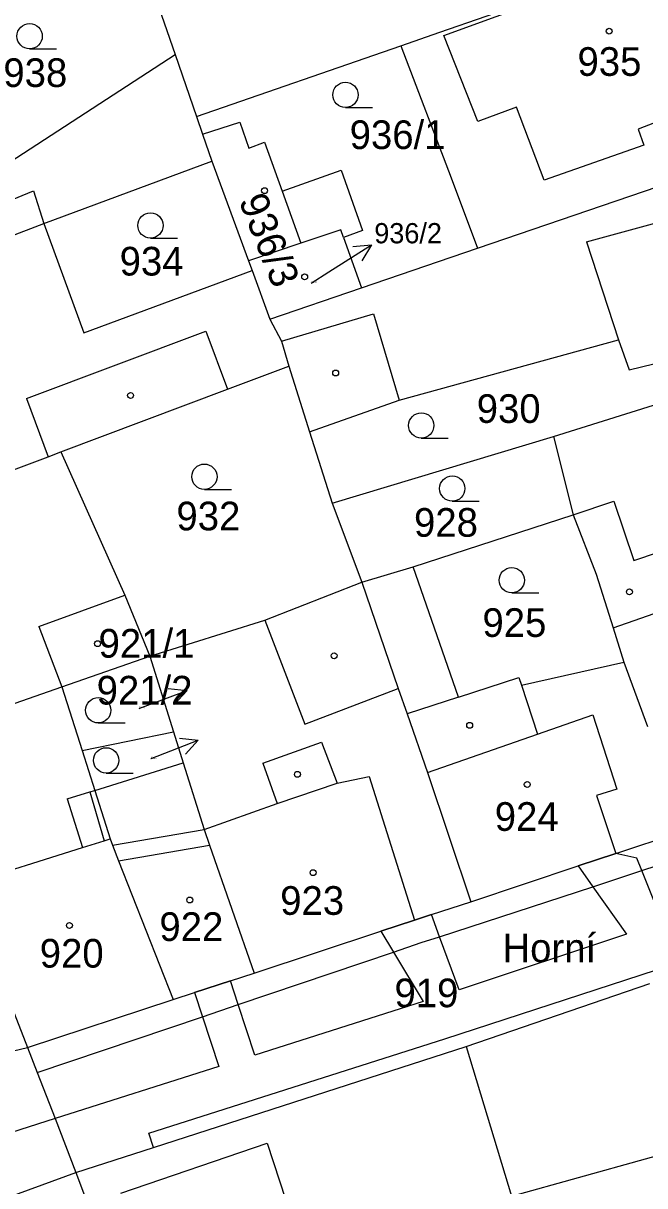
# Model space of a CAD drawing. Extents: x -785744 to -782822, y -1067550 to -1063910.
# Drawn here: x -783686.8 to -783649.9, y -1066020.9 to -1065951.9 of the extents above; entities that cross this region are included whole.
import ezdxf

# ---------------------------------------------------------------- set-up
doc = ezdxf.new("R2010")
doc.units = 0
for name, color, linetype in [('Hranice parcel', 7, 'Continuous'), ('Parcelní čísla', 7, 'Continuous'), ('Pop_ČP_popisy', 7, 'Continuous'), ('Vnitřní kresba', 7, 'Continuous'), ('Věcná břemena k části', 7, 'Continuous'), ('Značky budov', 7, 'Continuous'), ('Značky kultur', 7, 'Continuous')]:
    doc.layers.add(name, color=color, linetype=linetype)

msp = doc.modelspace()

# ---------------------------------------------------------------- linework, layer by layer
at = {"layer": 'Hranice parcel'}
for p, q in [((-783676.54, -1065957.47), (-783676.18, -1065958.51)), ((-783676.18, -1065958.51), (-783673.97, -1065957.81)), ((-783673.97, -1065957.81), (-783673.43, -1065959.34)), ((-783676.18, -1065958.51), (-783675.63, -1065960.11)), ((-783673.43, -1065959.34), (-783672.5, -1065959)), ((-783672.5, -1065959), (-783671.45, -1065961.89)), ((-783675.63, -1065960.11), (-783673.45, -1065966.02)), ((-783671.45, -1065961.89), (-783667.95, -1065960.66)), ((-783667.95, -1065960.66), (-783666.68, -1065964.23)), ((-783667.98, -1065964.19), (-783670.34, -1065964.98)), ((-783667.82, -1065964.64), (-783667.98, -1065964.19)), ((-783666.68, -1065964.23), (-783667.82, -1065964.64)), ((-783667.82, -1065964.64), (-783666.74, -1065967.63)), ((-783670.34, -1065964.98), (-783673.45, -1065966.02)), ((-783666.74, -1065967.63), (-783659.86, -1065965.28)), ((-783673.45, -1065966.02), (-783673.23, -1065966.61)), ((-783672.18, -1065969.49), (-783666.74, -1065967.63)), ((-783660.99, -1065991.9), (-783663.69, -1065984.17)), ((-783657.25, -1065991.2), (-783651.17, -1065989.82)), ((-783660.99, -1065991.9), (-783657.41, -1065990.73)), ((-783657.41, -1065990.73), (-783657.25, -1065991.2)), ((-783664.57, -1065991.38), (-783664.04, -1065992.9)), ((-783664.04, -1065992.9), (-783662.84, -1065996.36))]:
    msp.add_line(p, q, dxfattribs=at)
for points in [[(-783680.07, -1065947.23), (-783677.8, -1065953.8)], [(-783662.09, -1065952.47), (-783656.6, -1065950.57)], [(-783664.42, -1065953.28), (-783662.09, -1065952.47)], [(-783676.54, -1065957.47), (-783664.42, -1065953.28)], [(-783664.42, -1065953.28), (-783661.42, -1065961.11)], [(-783690.51, -1065962.03), (-783677.8, -1065953.8)], [(-783677.8, -1065953.8), (-783676.54, -1065957.47)], [(-783659.86, -1065965.28), (-783643.4, -1065959.66)], [(-783685.59, -1065963.82), (-783675.63, -1065960.11)], [(-783661.42, -1065961.11), (-783659.86, -1065965.28)], [(-783690.3, -1065965.62), (-783685.59, -1065963.82)], [(-783685.59, -1065963.82), (-783683.22, -1065970.29)], [(-783683.22, -1065970.29), (-783673.23, -1065966.61)], [(-783673.23, -1065966.61), (-783672.18, -1065969.49)], [(-783672.18, -1065969.49), (-783671.5, -1065970.8)], [(-783671.5, -1065970.8), (-783671.05, -1065972.27)], [(-783664.52, -1065974.29), (-783651.5, -1065970.71)], [(-783651.5, -1065970.71), (-783650.86, -1065972.5)], [(-783650.86, -1065972.5), (-783646.4, -1065971.4)], [(-783674.7, -1065973.64), (-783671.05, -1065972.27)], [(-783671.05, -1065972.27), (-783669.84, -1065976.17)], [(-783684.59, -1065977.36), (-783674.7, -1065973.64)], [(-783669.84, -1065976.17), (-783664.52, -1065974.29)], [(-783655.35, -1065976.45), (-783646.45, -1065973.65)], [(-783669.84, -1065976.17), (-783668.49, -1065980.39)], [(-783668.49, -1065980.39), (-783655.35, -1065976.45)], [(-783655.35, -1065976.45), (-783654.18, -1065981.09)], [(-783689.79, -1065979.32), (-783685.34, -1065977.65)], [(-783685.34, -1065977.65), (-783684.59, -1065977.36)], [(-783684.59, -1065977.36), (-783680.8, -1065985.85)], [(-783668.49, -1065980.39), (-783666.72, -1065985.08)], [(-783663.69, -1065984.17), (-783654.18, -1065981.09)], [(-783654.18, -1065981.09), (-783652.83, -1065984.61)], [(-783666.72, -1065985.08), (-783663.69, -1065984.17)], [(-783652.83, -1065984.61), (-783651.82, -1065987.8)], [(-783672.48, -1065987.34), (-783666.72, -1065985.08)], [(-783666.72, -1065985.08), (-783664.57, -1065991.38)], [(-783680.8, -1065985.85), (-783679.3, -1065989.47)], [(-783651.82, -1065987.8), (-783648.13, -1065986.51)], [(-783679.3, -1065989.47), (-783672.48, -1065987.34)], [(-783651.82, -1065987.8), (-783651.17, -1065989.82)], [(-783684.53, -1065991.29), (-783679.3, -1065989.47)], [(-783679.3, -1065989.47), (-783677.9, -1065993.96)], [(-783651.17, -1065989.82), (-783649.78, -1065993.65)], [(-783691.34, -1065993.67), (-783684.53, -1065991.29)], [(-783684.53, -1065991.29), (-783683.33, -1065995.06)], [(-783683.33, -1065995.06), (-783677.9, -1065993.96)], [(-783677.9, -1065993.96), (-783677.33, -1065995.79)], [(-783683.33, -1065995.06), (-783682.58, -1065997.43)], [(-783682.58, -1065997.43), (-783677.33, -1065995.79)], [(-783677.33, -1065995.79), (-783676.09, -1065999.75)], [(-783662.84, -1065996.36), (-783660.26, -1066004.04)], [(-783682.58, -1065997.43), (-783681.67, -1066000.31)], [(-783676.09, -1065999.75), (-783675.76, -1066000.67)], [(-783681.67, -1066000.31), (-783681.52, -1066000.68)], [(-783651.66, -1066001.17), (-783647.96, -1065999.94)], [(-783681.52, -1066000.68), (-783681.16, -1066001.6)], [(-783675.76, -1066000.67), (-783673.12, -1066008.26)], [(-783660.26, -1066004.04), (-783653.88, -1066001.91), (-783651.66, -1066001.17)], [(-783681.16, -1066001.6), (-783677.93, -1066009.84)], [(-783690.35, -1066003.03), (-783689.72, -1066004.62), (-783688.9, -1066006.72), (-783686.56, -1066012.68)], [(-783663.61, -1066005.13), (-783662.6, -1066004.8), (-783660.26, -1066004.04)], [(-783673.12, -1066008.26), (-783665.59, -1066005.78), (-783663.61, -1066005.13)], [(-783677.93, -1066009.84), (-783676.66, -1066009.42), (-783674.53, -1066008.72), (-783673.12, -1066008.26)], [(-783660.54, -1066012.61), (-783649.64, -1066008.89)], [(-783686.56, -1066012.68), (-783677.93, -1066009.84)], [(-783689.58, -1066013.38), (-783686.56, -1066012.68)], [(-783686.56, -1066012.68), (-783685.99, -1066014.16)], [(-783683.69, -1066020.08), (-783679.09, -1066018.6), (-783660.54, -1066012.61)], [(-783660.54, -1066012.61), (-783657.85, -1066021.5)], [(-783685.99, -1066014.16), (-783684.93, -1066016.89), (-783683.69, -1066020.08)], [(-783681.03, -1066021.32), (-783672.35, -1066018.35)], [(-783672.35, -1066018.35), (-783669.78, -1066026.19)], [(-783657.85, -1066021.5), (-783645.91, -1066018.18)], [(-783683.69, -1066020.08), (-783680.11, -1066029.6)]]:
    msp.add_lwpolyline(points, dxfattribs=at)
at = {"layer": 'Pop_ČP_popisy'}
for p, q in [((-783668.68, -1065966.68), (-783666.144, -1065965.077)), ((-783679.91, -1065992.56), (-783677.098, -1065991.514)), ((-783679.23, -1065995.53), (-783676.432, -1065994.448))]:
    msp.add_line(p, q, dxfattribs=at)
for points in [[(-783667.257, -1065965.188), (-783666.144, -1065965.077), (-783666.722, -1065966.034)], [(-783669.74, -1065967.35), (-783668.68, -1065966.68)], [(-783678.21, -1065991.394), (-783677.098, -1065991.514), (-783677.861, -1065992.331)], [(-783679.95, -1065992.57), (-783679.91, -1065992.56)], [(-783677.545, -1065994.343), (-783676.432, -1065994.448), (-783677.184, -1065995.275)], [(-783679.25, -1065995.54), (-783679.23, -1065995.53)]]:
    msp.add_lwpolyline(points, dxfattribs=at)
at = {"layer": 'Vnitřní kresba'}
for p, q in [((-783661.86, -1065952.67), (-783647.99, -1065947.6)), ((-783659.84, -1065957.76), (-783661.86, -1065952.67)), ((-783644.83, -1065956.05), (-783650.33, -1065958.23)), ((-783657.54, -1065956.92), (-783659.84, -1065957.76)), ((-783655.9, -1065961.25), (-783657.54, -1065956.92)), ((-783650.33, -1065958.23), (-783650, -1065959.17)), ((-783650, -1065959.17), (-783655.9, -1065961.25)), ((-783671.45, -1065961.89), (-783670.34, -1065964.98)), ((-783657.25, -1065991.2), (-783656.3, -1065994.1)), ((-783660.99, -1065991.9), (-783664.04, -1065992.9)), ((-783656.3, -1065994.1), (-783653.01, -1065992.96)), ((-783653.01, -1065992.96), (-783651.6, -1065997.35)), ((-783662.84, -1065996.36), (-783656.3, -1065994.1)), ((-783651.6, -1065997.35), (-783652.8, -1065997.73)), ((-783652.8, -1065997.73), (-783651.66, -1066001.17))]:
    msp.add_line(p, q, dxfattribs=at)
for points in [[(-783690.97, -1065963.83), (-783686.22, -1065961.88)], [(-783686.22, -1065961.88), (-783685.59, -1065963.82)], [(-783653.4, -1065964.9), (-783648.6, -1065963.6)], [(-783653.4, -1065964.9), (-783651.5, -1065970.71)], [(-783671.5, -1065970.8), (-783666.03, -1065969.18)], [(-783666.03, -1065969.18), (-783664.52, -1065974.29)], [(-783686.63, -1065974.2), (-783675.99, -1065970.2)], [(-783675.99, -1065970.2), (-783674.7, -1065973.64)], [(-783686.63, -1065974.2), (-783685.34, -1065977.65)], [(-783654.18, -1065981.09), (-783651.77, -1065980.28)], [(-783651.77, -1065980.28), (-783650.59, -1065983.79)], [(-783650.59, -1065983.79), (-783647.72, -1065982.83)], [(-783685.9, -1065987.72), (-783680.8, -1065985.85)], [(-783672.48, -1065987.34), (-783670.1, -1065993.51)], [(-783685.9, -1065987.72), (-783684.53, -1065991.29)], [(-783670.1, -1065993.51), (-783664.57, -1065991.38)], [(-783672.6, -1065995.81), (-783669.12, -1065994.58)], [(-783669.12, -1065994.58), (-783668.2, -1065997)], [(-783663.2, -1066006.46), (-783662.12, -1066006.11), (-783653.01, -1066003.14), (-783650.11, -1066002.19), (-783629.52, -1065995.48)], [(-783672.6, -1065995.81), (-783671.75, -1065998.21)], [(-783671.75, -1065998.21), (-783668.2, -1065997)], [(-783668.2, -1065997), (-783666.3, -1065996.6)], [(-783666.3, -1065996.6), (-783663.61, -1066005.13)], [(-783684.21, -1065997.94), (-783682.87, -1065997.52)], [(-783682.87, -1065997.52), (-783682.58, -1065997.43)], [(-783682.87, -1065997.52), (-783682.01, -1066000.42)], [(-783684.21, -1065997.94), (-783683.31, -1066000.82)], [(-783676.09, -1065999.75), (-783671.75, -1065998.21)], [(-783681.52, -1066000.68), (-783676.09, -1065999.75)], [(-783683.31, -1066000.82), (-783682.01, -1066000.42)], [(-783682.01, -1066000.42), (-783681.67, -1066000.31)], [(-783690.35, -1066003.03), (-783683.31, -1066000.82)], [(-783681.16, -1066001.6), (-783675.76, -1066000.67)], [(-783685.99, -1066014.16), (-783676.19, -1066010.85), (-783674.06, -1066010.13), (-783664.85, -1066007.02), (-783663.2, -1066006.46)]]:
    msp.add_lwpolyline(points, dxfattribs=at)
at = {"layer": 'Věcná břemena k části'}
for points in [[(-783651.66, -1066001.17), (-783653.88, -1066001.91)], [(-783650.41, -1066001.44), (-783651.66, -1066001.17)], [(-783650.11, -1066002.19), (-783650.41, -1066001.44)], [(-783661.81, -1066012.17), (-783630.43, -1066001.95)], [(-783653.88, -1066001.91), (-783653.01, -1066003.14)], [(-783648.88, -1066005.24), (-783650.11, -1066002.19)], [(-783653.01, -1066003.14), (-783651.02, -1066005.95)], [(-783663.61, -1066005.13), (-783665.59, -1066005.78)], [(-783662.6, -1066004.8), (-783663.61, -1066005.13)], [(-783662.12, -1066006.11), (-783662.6, -1066004.8)], [(-783665.59, -1066005.78), (-783664.85, -1066007.02)], [(-783651.02, -1066005.95), (-783660.95, -1066009.25)], [(-783660.95, -1066009.25), (-783662.12, -1066006.11)], [(-783664.85, -1066007.02), (-783663.09, -1066009.95)], [(-783674.53, -1066008.72), (-783676.66, -1066009.42)], [(-783674.06, -1066010.13), (-783674.53, -1066008.72)], [(-783676.66, -1066009.42), (-783676.19, -1066010.85)], [(-783673.07, -1066013.13), (-783674.06, -1066010.13)], [(-783663.09, -1066009.95), (-783673.07, -1066013.13)], [(-783676.19, -1066010.85), (-783675.22, -1066013.81)], [(-783679.37, -1066017.75), (-783661.81, -1066012.17)], [(-783675.22, -1066013.81), (-783684.93, -1066016.89)], [(-783684.93, -1066016.89), (-783690.75, -1066018.74)], [(-783679.09, -1066018.6), (-783679.37, -1066017.75)], [(-783683.69, -1066020.08), (-783679.09, -1066018.6)], [(-783691.92, -1066023.1), (-783683.69, -1066020.08)]]:
    msp.add_lwpolyline(points, dxfattribs=at)
at = {"layer": 'Značky budov'}
for centre in [(-783652.05, -1065952.41), (-783672.5, -1065961.87), (-783670.12, -1065966.98), (-783668.28, -1065972.68), (-783680.45, -1065974.01), (-783650.85, -1065985.66), (-783682.41, -1065988.73), (-783668.37, -1065989.45), (-783660.33, -1065993.57), (-783670.55, -1065996.48), (-783656.91, -1065997.08), (-783669.62, -1066002.31), (-783676.94, -1066003.93), (-783684.08, -1066005.44)]:
    msp.add_circle(centre, 0.175, dxfattribs=at)
at = {"layer": 'Značky kultur'}
for p, q in [((-783686.44, -1065953.46), (-783684.84, -1065953.46)), ((-783667.7, -1065956.94), (-783666.1, -1065956.94)), ((-783679.27, -1065964.68), (-783677.67, -1065964.68)), ((-783663.2, -1065976.54), (-783661.6, -1065976.54)), ((-783676.07, -1065979.58), (-783674.47, -1065979.58)), ((-783661.36, -1065980.28), (-783659.76, -1065980.28)), ((-783657.83, -1065985.72), (-783656.23, -1065985.72)), ((-783682.37, -1065993.43), (-783680.77, -1065993.43)), ((-783681.9, -1065996.4), (-783680.3, -1065996.4))]:
    msp.add_line(p, q, dxfattribs=at)
for centre in [(-783686.44, -1065952.71), (-783667.7, -1065956.19), (-783679.27, -1065963.93), (-783663.2, -1065975.79), (-783676.07, -1065978.83), (-783661.36, -1065979.53), (-783657.83, -1065984.97), (-783682.37, -1065992.68), (-783681.9, -1065995.65)]:
    msp.add_circle(centre, 0.75, dxfattribs=at)

# ---------------------------------------------------------------- texts
at = {"layer": 'Parcelní čísla'}
for s, height, p in [('935', 1.7, (-783653.93, -1065955.06)), ('938', 1.7, (-783688, -1065955.72)), ('936/1', 1.7, (-783667.45, -1065959.4)), ('934', 1.7, (-783681.1, -1065966.9)), ('936/2', 0.1, (-783669.74, -1065967.35)), ('930', 1.7, (-783659.91, -1065975.64)), ('932', 1.7, (-783677.73, -1065982.01)), ('928', 1.7, (-783663.63, -1065982.39)), ('925', 1.7, (-783659.57, -1065988.33)), ('921/1', 0.1, (-783679.95, -1065992.57)), ('921/2', 0.1, (-783679.25, -1065995.54)), ('924', 1.7, (-783658.84, -1065999.83)), ('923', 1.7, (-783671.57, -1066004.81)), ('922', 1.7, (-783678.74, -1066006.36)), ('920', 1.7, (-783685.84, -1066007.94)), ('919', 1.7, (-783664.79, -1066010.29))]:
    msp.add_text(s, height=height, dxfattribs=at).set_placement(p)
msp.add_text('936/3', height=1.7, rotation=291.6, dxfattribs=at).set_placement((-783674.05, -1065962.45))
at = {"layer": 'Pop_ČP_popisy'}
for s, height, p in [('936/2', 1.2, (-783665.99, -1065964.99)), ('921/1', 1.7, (-783682.35, -1065989.56)), ('921/2', 1.7, (-783682.464, -1065992.34)), ('Horní', 1.7, (-783658.38, -1066007.62))]:
    msp.add_text(s, height=height, dxfattribs=at).set_placement(p)

doc.saveas('drawing.dxf')
